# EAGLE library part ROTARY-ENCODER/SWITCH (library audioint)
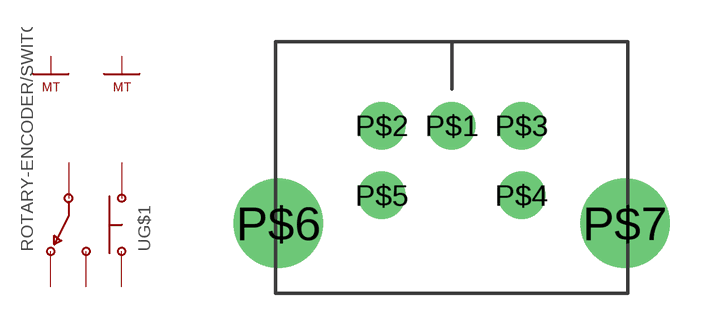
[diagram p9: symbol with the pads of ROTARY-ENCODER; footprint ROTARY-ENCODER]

Designator prefix -; gates G$1=ROTARY-ENCODER/SWITCH G$2=MECHANICAL G$3=MECHANICAL

## ROTARY-ENCODER/SWITCHSWITCH  [ROTARY-ENCODER]
P$1  G$1:P$5
P$2  G$1:P$1
P$3  G$1:P$2
P$4  G$1:P$4
P$5  G$1:P$3
P$6  G$2:MT  pas
P$7  G$3:MT  pas

## Footprint ROTARY-ENCODER (pad centres in mm)
drill 1.092 pad 1.7 round: P$1 0,0; P$2 -2.5,0; P$3 2.5,0; P$4 2.5,-2.5; P$5 -2.5,-2.5
drill 2.108 pad 3.2 round: P$6 -6.2,-3.5; P$7 6.2,-3.5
